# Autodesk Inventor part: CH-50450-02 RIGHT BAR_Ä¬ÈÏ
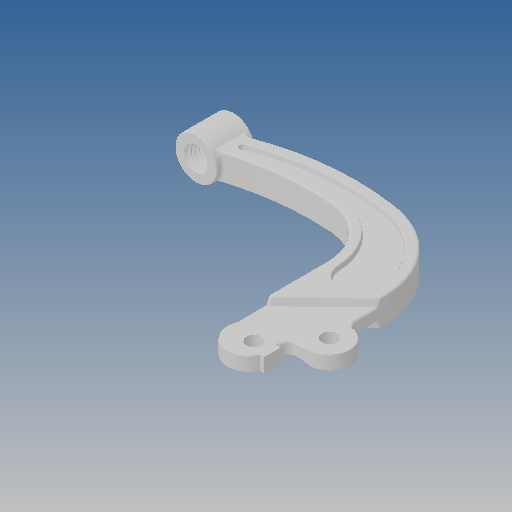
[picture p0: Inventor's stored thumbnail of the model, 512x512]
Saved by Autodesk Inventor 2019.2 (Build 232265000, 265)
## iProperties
Created: 2010-06
Part Number: CH-50450-02 RIGHT BAR_Ä¬ÈÏ
Material: Ogólny
Document SubType Name: Modeling
Designer: CADENGINEERING4
Density: 1 g/cm^3
Appearance: Domyślna
Author: CADENGINEERING4
Revision Number: ÈÎºÎ
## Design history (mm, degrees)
feature "NONE"
node "Bryła1"
